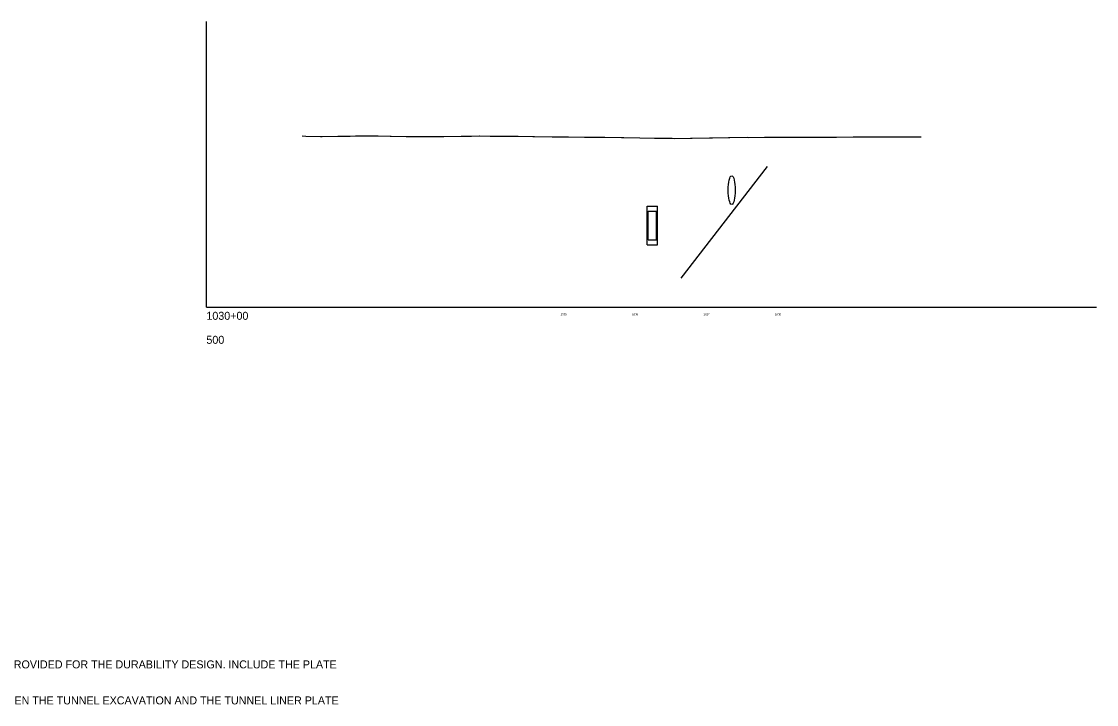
# Model space of a CAD drawing. Extents: x 2047712 to 2051245, y 280285 to 283042.
# Drawn here: x 2049741 to 2051245, y 280356 to 281312 of the extents above; entities that cross this region are included whole.
import ezdxf

# ---------------------------------------------------------------- set-up
doc = ezdxf.new("R2010")
doc.units = 0
for name, color, linetype in [('Default', 7, 'Continuous'), ('DR_X_Storm_Sewer', 7, 'Continuous'), ('PV_X_Driveway', 7, 'Continuous'), ('RW_X_CL_100_Curve_Data', 7, 'Continuous'), ('SV_X_Mon_Cells_Found', 7, 'Continuous'), ('UT_X_Water_Cells', 7, 'Continuous')]:
    doc.layers.add(name, color=color, linetype=linetype)

msp = doc.modelspace()

# ---------------------------------------------------------------- linework, layer by layer
at = {"layer": 'Default'}
msp.add_line((2049999.6, 280911.8), (2049999.6, 281311.8), dxfattribs=at)
at = {"layer": 'DR_X_Storm_Sewer'}
msp.add_line((2050664.1, 280952.5), (2050784.8, 281108.9), dxfattribs=at)
at = {"layer": 'PV_X_Driveway'}
msp.add_line((2049999.6, 280911.8), (2051245, 280911.8), dxfattribs=at)
at = {"layer": 'RW_X_CL_100_Curve_Data'}
msp.add_ellipse((2050734.6, 281075.8), major_axis=(0, 20), ratio=0.25, dxfattribs=at)
at = {"layer": 'SV_X_Mon_Cells_Found'}
for p, q in [((2050616.4, 280999.3), (2050616.4, 281053.3)), ((2050616.4, 281053.3), (2050630.9, 281053.3)), ((2050630.9, 280999.3), (2050630.9, 281053.3)), ((2050617.6, 281006.3), (2050617.6, 281046.3)), ((2050617.6, 281046.3), (2050629.6, 281046.3)), ((2050629.6, 281006.3), (2050629.6, 281046.3)), ((2050617.6, 281006.3), (2050629.6, 281006.3)), ((2050616.4, 280999.3), (2050630.9, 280999.3))]:
    msp.add_line(p, q, dxfattribs=at)
at = {"layer": 'UT_X_Water_Cells'}
msp.add_lwpolyline([(2050133.6, 281151.6), (2050133.7, 281151.6), (2050138.7, 281151.5), (2050159.4, 281151), (2050159.9, 281151), (2050161.8, 281151), (2050183.5, 281151.1), (2050184.4, 281151.1), (2050200.9, 281151.5), (2050208.1, 281151.7), (2050209.6, 281151.7), (2050232.5, 281151.7), (2050233.9, 281151.7), (2050240.1, 281151.6), (2050256.6, 281151.3), (2050258.2, 281151.2), (2050279.3, 281151), (2050281.8, 281151), (2050283.5, 281151), (2050285, 281151), (2050308.3, 281150.8), (2050308.8, 281150.8), (2050318.4, 281150.8), (2050331.1, 281150.7), (2050331.4, 281150.7), (2050331.6, 281150.7), (2050331.7, 281150.7), (2050355.9, 281151.2), (2050356, 281151.2), (2050356, 281151.2), (2050356.2, 281151.3), (2050357.6, 281151.3), (2050370.5, 281151.4), (2050381.9, 281151.6), (2050382.1, 281151.6), (2050396.8, 281151.4), (2050405.2, 281151.4), (2050406.2, 281151.4), (2050431.9, 281151.2), (2050433.7, 281151.1), (2050435.9, 281151.1), (2050456.4, 281150.8), (2050458.5, 281150.8), (2050483.6, 281150.5), (2050485.9, 281150.4), (2050506.1, 281150.2), (2050528.9, 281150.1), (2050531.4, 281150), (2050552.2, 281150), (2050554.6, 281150), (2050557, 281149.9), (2050580.6, 281149.5), (2050583.6, 281149.4), (2050606.3, 281148.8), (2050626.4, 281148.4), (2050628.5, 281148.4), (2050651.5, 281148.3), (2050653.9, 281148.2), (2050676.9, 281148.5), (2050679.3, 281148.5), (2050703.5, 281148.9), (2050705.6, 281149), (2050707.6, 281149), (2050730, 281149.4), (2050731.8, 281149.4), (2050756.4, 281149.7), (2050758.1, 281149.6), (2050780.7, 281149.7), (2050782.4, 281149.7), (2050806.9, 281149.8), (2050808.3, 281149.8), (2050830.1, 281150), (2050831.5, 281150), (2050855.7, 281150), (2050857.1, 281150), (2050880, 281150.1), (2050881.1, 281150.1), (2050904.4, 281150.2), (2050905.2, 281150.2), (2050927.6, 281150.3), (2050928.6, 281150.3), (2050954.2, 281150.4), (2050954.8, 281150.4), (2050979.3, 281150.4), (2050979.8, 281150.4), (2050999.6, 281150.5)], dxfattribs=at)

# ---------------------------------------------------------------- texts
at = {"layer": 'Default'}
for s, p in [('1030+00', (2049999.7, 280894.3)), ('500', (2049999.7, 280860.7)), ('PROVIDE GALVANIZED STEEL OR ALUMINUM TUNNEL LINER PLATE MANUFACTURED BY: DSI TUNNELING, LLC; CONTECH ENGINEERED SOLUTIONS, LLC.; OR AN APPROVED EQUAL. THE MINIMUM THICKNESS SHOWN IN THE PLANS IS PROVIDED FOR THE DURABILITY DESIGN. INCLUDE THE PLATE ', (2048009.2, 280406.4)), ('PROVIDE MATERIAL FOR GALVANIZED STEEL TUNNEL LINER PLATE PER 707.03. PROVIDE MATERIAL FOR ALUMINUM TUNNEL LINER PLATE PER 707.23. PROVIDE CONCRETE FIELD PAVING PER 611.11. FILL THE ANNULAR SPACE BETWEEN THE TUNNEL EXCAVATION AND THE TUNNEL LINER PLATE ', (2048009.2, 280356))]:
    msp.add_text(s, height=11.2, dxfattribs=at).set_placement(p)
at = {"layer": 'PV_X_Driveway'}
for s, p in [('1035', (2050495.2, 280900.5)), ('1036', (2050595.1, 280900.5)), ('1037', (2050695.1, 280900.5)), ('1038', (2050795.1, 280900.5))]:
    msp.add_text(s, height=2.8, dxfattribs=at).set_placement(p)

doc.saveas('drawing.dxf')
